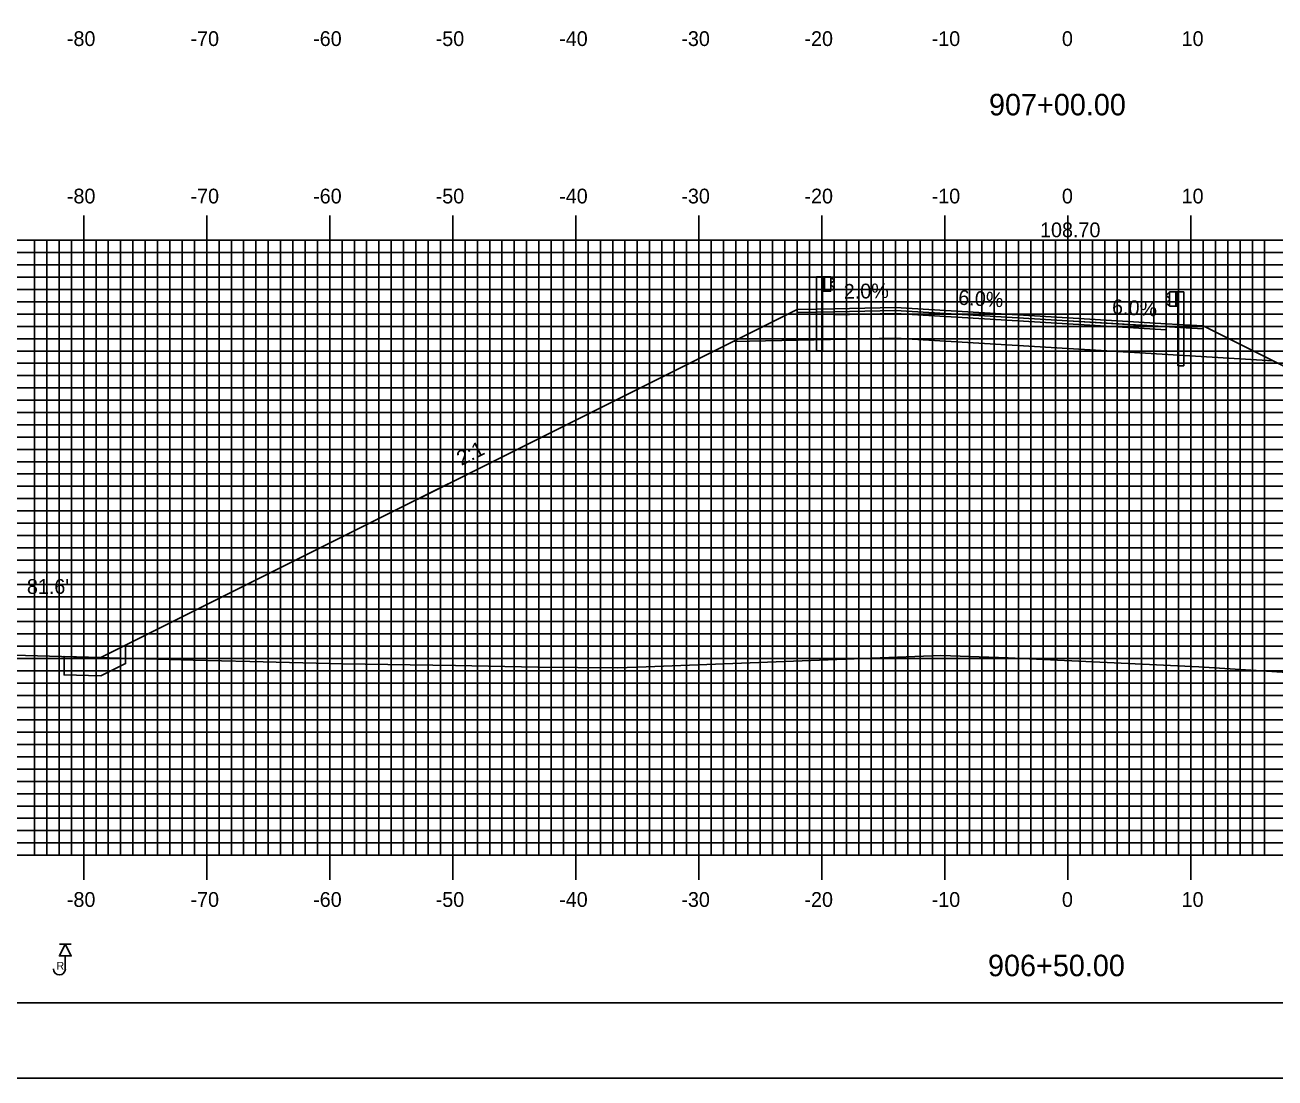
# Model space of a CAD drawing. Extents: x 857897 to 858240, y 364765 to 364985.
# Drawn here: x 857978 to 858079.7, y 364765.2 to 364850.8 of the extents above; entities that cross this region are included whole.
import ezdxf

# ---------------------------------------------------------------- set-up
doc = ezdxf.new("R2010")
doc.units = 0
for name, color, linetype in [('ANNOTATION', 7, 'Continuous'), ('BORDER', 7, 'Continuous'), ('BORING - REFUSAL', 7, 'Continuous'), ('D_Guardrail_Beam_Lt', 7, 'Continuous'), ('D_Guardrail_Beam_Rt', 7, 'Continuous'), ('D_Roadway_Centerline', 7, 'Continuous'), ('D_Roadway_Centerline_Text', 7, 'Continuous'), ('D_Roadway_Edge_Shoulder', 7, 'Continuous'), ('D_Roadway_Edge_TW', 7, 'Continuous'), ('D_Roadway_FinishedGrade', 7, 'Continuous'), ('D_Roadway_Pavement', 7, 'Continuous'), ('D_Roadway_SlopeLines', 7, 'Continuous'), ('D_Roadway_SubGrade', 7, 'Continuous'), ('D_Text_Standard', 7, 'Continuous'), ('H_V ANNOTATION', 7, 'Continuous'), ('MAJOR', 7, 'Continuous'), ('MINOR', 7, 'Continuous'), ('PLOT BOUNDARY', 7, 'Continuous'), ('S_Roadway_Centerline', 7, 'Continuous')]:
    doc.layers.add(name, color=color, linetype=linetype)

msp = doc.modelspace()

# ---------------------------------------------------------------- linework, layer by layer
at = {"layer": 'BORDER'}
msp.add_lwpolyline([(857913.22, 364771.3), (858233.22, 364771.3), (858233.22, 364981.3), (857913.22, 364981.3)], close=True, dxfattribs=at)
at = {"layer": 'BORING - REFUSAL'}
for p, q in [((857981.8, 364776.07), (857980.84, 364776.07)), ((857981.32, 364775.11), (857981.32, 364774.05))]:
    msp.add_line(p, q, dxfattribs=at)
msp.add_lwpolyline([(857981.32, 364776.07), (857981.8, 364775.11), (857980.84, 364775.11)], close=True, dxfattribs=at)
msp.add_arc((857980.84, 364774.05), 0.485, 180, 0, dxfattribs=at)
at = {"layer": 'D_Guardrail_Beam_Lt'}
for p, q in [((858042.39, 364830.32), (858042.39, 364824.32)), ((858042.86, 364830.32), (858042.39, 364830.32)), ((858043.55, 364830.32), (858042.86, 364830.32)), ((858042.86, 364830.32), (858042.86, 364829.16)), ((858042.92, 364830.32), (858042.92, 364829.16)), ((858043.03, 364830.32), (858043.03, 364829.16)), ((858043.55, 364829.16), (858043.55, 364830.32)), ((858043.55, 364830.24), (858043.62, 364830.22)), ((858043.55, 364829.77), (858043.55, 364829.7)), ((858043.78, 364829.97), (858043.59, 364829.84)), ((858043.59, 364829.64), (858043.78, 364829.5)), ((858043.64, 364830.22), (858043.78, 364830.12)), ((858042.86, 364829.16), (858043.55, 364829.16)), ((858042.88, 364824.32), (858042.88, 364829.16)), ((858043.62, 364829.25), (858043.55, 364829.24)), ((858043.78, 364829.36), (858043.64, 364829.26)), ((858042.88, 364824.32), (858042.39, 364824.32))]:
    msp.add_line(p, q, dxfattribs=at)
for centre, major_axis, start_param, end_param in [((858043.63, 364829.77), (-0.0789, 0), 5.323254, 6.283185), ((858043.63, 364829.7), (-0.0789, 0), 6.283185, 7.243116), ((858043.62, 364830.18), (0.0417, 0), 0.959931, 1.376053), ((858043.73, 364830.05), (0.0877, 0), 5.323254, 7.243116), ((858043.62, 364829.29), (0.0417, 0), 4.907132, 5.323254), ((858043.73, 364829.43), (0.0877, 0), 5.323254, 7.243116)]:
    msp.add_ellipse(centre, major_axis=major_axis, ratio=0.995501, start_param=start_param, end_param=end_param, dxfattribs=at)
at = {"layer": 'D_Guardrail_Beam_Rt'}
for p, q in [((858071, 364829), (858070.86, 364828.9)), ((858070.86, 364828.75), (858071.05, 364828.62)), ((858071.09, 364829.02), (858071.02, 364829)), ((858071.09, 364829.1), (858071.78, 364829.1)), ((858071.09, 364827.94), (858071.09, 364829.1)), ((858071.61, 364829.1), (858071.61, 364827.94)), ((858071.72, 364829.1), (858071.72, 364827.94)), ((858071.78, 364829.1), (858072.25, 364829.1)), ((858071.78, 364829.1), (858071.78, 364827.94)), ((858072.25, 364829.1), (858072.25, 364823.1)), ((858071.05, 364828.42), (858070.86, 364828.28)), ((858070.86, 364828.14), (858071, 364828.04)), ((858071.02, 364828.03), (858071.09, 364828.02)), ((858071.09, 364828.55), (858071.09, 364828.48)), ((858071.78, 364827.94), (858071.09, 364827.94)), ((858071.76, 364823.1), (858071.76, 364827.94)), ((858071.76, 364823.1), (858072.25, 364823.1))]:
    msp.add_line(p, q, dxfattribs=at)
for centre, major_axis, start_param, end_param in [((858070.91, 364828.83), (-0.0877, 0), 5.323254, 7.243116), ((858071.03, 364828.96), (-0.0417, 0), 4.907132, 5.323254), ((858071.01, 364828.55), (0.0789, 0), 0, 0.959931), ((858070.91, 364828.21), (-0.0877, 0), 5.323254, 7.243116), ((858071.03, 364828.07), (-0.0417, 0), 0.959931, 1.376053), ((858071.01, 364828.48), (0.0789, 0), 5.323254, 6.283185)]:
    msp.add_ellipse(centre, major_axis=major_axis, ratio=0.995501, start_param=start_param, end_param=end_param, dxfattribs=at)
at = {"layer": 'D_Roadway_Centerline'}
msp.add_lwpolyline([(857984.22, 364799.38), (858035.61, 364825.07), (858040.82, 364827.68), (858043.82, 364827.74), (858048.82, 364827.84), (858062.82, 364827), (858070.82, 364826.52), (858073.82, 364826.34), (858079.5, 364823.5), (858128.75, 364798.87)], dxfattribs=at)
at = {"layer": 'D_Roadway_Edge_Shoulder'}
for points in [[(858048.82, 364827.84), (858043.82, 364827.74), (858043.82, 364827.74), (858040.82, 364827.68), (858040.82, 364827.43), (858043.82, 364827.49), (858048.82, 364827.59)], [(858062.82, 364827), (858070.82, 364826.52), (858070.82, 364826.52), (858073.82, 364826.34), (858073.82, 364826.09), (858062.82, 364826.75)]]:
    msp.add_lwpolyline(points, close=True, dxfattribs=at)
at = {"layer": 'D_Roadway_Edge_TW'}
msp.add_lwpolyline([(858048.82, 364827.84), (858062.82, 364827), (858062.82, 364826.75), (858048.82, 364827.59)], close=True, dxfattribs=at)
at = {"layer": 'D_Roadway_FinishedGrade'}
for points in [[(857986.22, 364800.38), (857986.22, 364798.88), (857984.22, 364797.88), (857981.22, 364797.96), (857981.22, 364799.46), (857984.22, 364799.38)], [(857981.22, 364799.46), (857981.22, 364797.96), (857984.22, 364797.88), (857986.22, 364798.88), (857986.22, 364800.38), (857984.22, 364799.38)]]:
    msp.add_lwpolyline(points, close=True, dxfattribs=at)
at = {"layer": 'D_Roadway_Pavement'}
for points in [[(858048.82, 364827.59), (858043.82, 364827.49), (858043.82, 364827.24), (858048.82, 364827.34)], [(858048.82, 364827.59), (858062.82, 364826.75), (858062.82, 364826.5), (858048.82, 364827.34)]]:
    msp.add_lwpolyline(points, close=True, dxfattribs=at)
for points in [[(858062.82, 364826.75), (858062.82, 364826.5)], [(858062.82, 364826.75), (858062.82, 364826.5)], [(858062.82, 364826.75), (858062.82, 364826.5)], [(858062.82, 364826.75), (858070.82, 364826.27), (858070.82, 364826.02), (858062.82, 364826.5)]]:
    msp.add_lwpolyline(points, dxfattribs=at)
at = {"layer": 'D_Roadway_SlopeLines'}
for points in [[(858040.82, 364827.68), (857984.22, 364799.38)], [(858073.82, 364826.34), (858128.75, 364798.87)]]:
    msp.add_lwpolyline(points, dxfattribs=at)
at = {"layer": 'D_Roadway_SubGrade'}
for points in [[(858048.82, 364827.34), (858043.82, 364827.24), (858043.82, 364827.49), (858040.82, 364827.43), (858040.82, 364827.68), (858035.61, 364825.07), (858048.82, 364825.34)], [(858048.82, 364827.34), (858062.82, 364826.5), (858062.82, 364824.5), (858048.82, 364825.34)], [(858062.82, 364826.5), (858062.82, 364826.75), (858073.82, 364826.09), (858073.82, 364826.34), (858079.5, 364823.5), (858062.82, 364824.5)]]:
    msp.add_lwpolyline(points, close=True, dxfattribs=at)
at = {"layer": 'MAJOR'}
for p, q in [((857982.82, 364835.31), (857982.82, 364833.3)), ((857992.82, 364835.31), (857992.82, 364833.3)), ((858002.82, 364835.31), (858002.82, 364833.3)), ((858012.82, 364835.31), (858012.82, 364833.3)), ((858022.82, 364835.31), (858022.82, 364833.3)), ((858032.82, 364835.31), (858032.82, 364833.3)), ((858042.82, 364835.31), (858042.82, 364833.3)), ((858052.82, 364835.31), (858052.82, 364833.3)), ((858062.82, 364835.31), (858062.82, 364833.3)), ((858072.82, 364835.31), (858072.82, 364833.3)), ((857922.82, 364833.3), (858202.82, 364833.3)), ((857922.82, 364833.3), (858202.82, 364833.3)), ((857982.82, 364783.3), (857982.82, 364833.3)), ((857992.82, 364783.3), (857992.82, 364833.3)), ((858002.82, 364783.3), (858002.82, 364833.3)), ((858012.82, 364783.3), (858012.82, 364833.3)), ((858022.82, 364783.3), (858022.82, 364833.3)), ((858032.82, 364783.3), (858032.82, 364833.3)), ((858042.82, 364783.3), (858042.82, 364833.3)), ((858052.82, 364783.3), (858052.82, 364833.3)), ((858062.82, 364783.3), (858062.82, 364833.3)), ((858072.82, 364783.3), (858072.82, 364833.3)), ((857922.82, 364828.3), (858202.82, 364828.3)), ((857922.82, 364823.3), (858202.82, 364823.3)), ((857922.82, 364818.3), (858202.82, 364818.3)), ((857922.82, 364813.3), (858202.82, 364813.3)), ((857922.82, 364808.3), (858202.82, 364808.3)), ((857922.82, 364803.3), (858202.82, 364803.3)), ((857922.82, 364798.3), (858202.82, 364798.3)), ((857922.82, 364793.3), (858202.82, 364793.3)), ((857922.82, 364788.3), (858202.82, 364788.3)), ((857922.82, 364783.3), (858202.82, 364783.3)), ((857922.82, 364783.3), (858202.82, 364783.3)), ((857982.82, 364781.3), (857982.82, 364783.3)), ((857992.82, 364781.3), (857992.82, 364783.3)), ((858002.82, 364781.3), (858002.82, 364783.3)), ((858012.82, 364781.3), (858012.82, 364783.3)), ((858022.82, 364781.3), (858022.82, 364783.3)), ((858032.82, 364781.3), (858032.82, 364783.3)), ((858042.82, 364781.3), (858042.82, 364783.3)), ((858052.82, 364781.3), (858052.82, 364783.3)), ((858062.82, 364781.3), (858062.82, 364783.3)), ((858072.82, 364781.3), (858072.82, 364783.3))]:
    msp.add_line(p, q, dxfattribs=at)
at = {"layer": 'MINOR'}
for p, q in [((857978.82, 364783.3), (857978.82, 364833.3)), ((857979.82, 364783.3), (857979.82, 364833.3)), ((857980.82, 364783.3), (857980.82, 364833.3)), ((857981.82, 364783.3), (857981.82, 364833.3)), ((857983.82, 364783.3), (857983.82, 364833.3)), ((857984.82, 364783.3), (857984.82, 364833.3)), ((857985.82, 364783.3), (857985.82, 364833.3)), ((857986.82, 364783.3), (857986.82, 364833.3)), ((857987.82, 364783.3), (857987.82, 364833.3)), ((857988.82, 364783.3), (857988.82, 364833.3)), ((857989.82, 364783.3), (857989.82, 364833.3)), ((857990.82, 364783.3), (857990.82, 364833.3)), ((857991.82, 364783.3), (857991.82, 364833.3)), ((857993.82, 364783.3), (857993.82, 364833.3)), ((857994.82, 364783.3), (857994.82, 364833.3)), ((857995.82, 364783.3), (857995.82, 364833.3)), ((857996.82, 364783.3), (857996.82, 364833.3)), ((857997.82, 364783.3), (857997.82, 364833.3)), ((857998.82, 364783.3), (857998.82, 364833.3)), ((857999.82, 364783.3), (857999.82, 364833.3)), ((858000.82, 364783.3), (858000.82, 364833.3)), ((858001.82, 364783.3), (858001.82, 364833.3)), ((858003.82, 364783.3), (858003.82, 364833.3)), ((858004.82, 364783.3), (858004.82, 364833.3)), ((858005.82, 364783.3), (858005.82, 364833.3)), ((858006.82, 364783.3), (858006.82, 364833.3)), ((858007.82, 364783.3), (858007.82, 364833.3)), ((858008.82, 364783.3), (858008.82, 364833.3)), ((858009.82, 364783.3), (858009.82, 364833.3)), ((858010.82, 364783.3), (858010.82, 364833.3)), ((858011.82, 364783.3), (858011.82, 364833.3)), ((858013.82, 364783.3), (858013.82, 364833.3)), ((858014.82, 364783.3), (858014.82, 364833.3)), ((858015.82, 364783.3), (858015.82, 364833.3)), ((858016.82, 364783.3), (858016.82, 364833.3)), ((858017.82, 364783.3), (858017.82, 364833.3)), ((858018.82, 364783.3), (858018.82, 364833.3)), ((858019.82, 364783.3), (858019.82, 364833.3)), ((858020.82, 364783.3), (858020.82, 364833.3)), ((858021.82, 364783.3), (858021.82, 364833.3)), ((858023.82, 364783.3), (858023.82, 364833.3)), ((858024.82, 364783.3), (858024.82, 364833.3)), ((858025.82, 364783.3), (858025.82, 364833.3)), ((858026.82, 364783.3), (858026.82, 364833.3)), ((858027.82, 364783.3), (858027.82, 364833.3)), ((858028.82, 364783.3), (858028.82, 364833.3)), ((858029.82, 364783.3), (858029.82, 364833.3)), ((858030.82, 364783.3), (858030.82, 364833.3)), ((858031.82, 364783.3), (858031.82, 364833.3)), ((858033.82, 364783.3), (858033.82, 364833.3)), ((858034.82, 364783.3), (858034.82, 364833.3)), ((858035.82, 364783.3), (858035.82, 364833.3)), ((858036.82, 364783.3), (858036.82, 364833.3)), ((858037.82, 364783.3), (858037.82, 364833.3)), ((858038.82, 364783.3), (858038.82, 364833.3)), ((858039.82, 364783.3), (858039.82, 364833.3)), ((858040.82, 364783.3), (858040.82, 364833.3)), ((858041.82, 364783.3), (858041.82, 364833.3)), ((858043.82, 364783.3), (858043.82, 364833.3)), ((858044.82, 364783.3), (858044.82, 364833.3)), ((858045.82, 364783.3), (858045.82, 364833.3)), ((858046.82, 364783.3), (858046.82, 364833.3)), ((858047.82, 364783.3), (858047.82, 364833.3)), ((858048.82, 364783.3), (858048.82, 364833.3)), ((858049.82, 364783.3), (858049.82, 364833.3)), ((858050.82, 364783.3), (858050.82, 364833.3)), ((858051.82, 364783.3), (858051.82, 364833.3)), ((858053.82, 364783.3), (858053.82, 364833.3)), ((858054.82, 364783.3), (858054.82, 364833.3)), ((858055.82, 364783.3), (858055.82, 364833.3)), ((858056.82, 364783.3), (858056.82, 364833.3)), ((858057.82, 364783.3), (858057.82, 364833.3)), ((858058.82, 364783.3), (858058.82, 364833.3)), ((858059.82, 364783.3), (858059.82, 364833.3)), ((858060.82, 364783.3), (858060.82, 364833.3)), ((858061.82, 364783.3), (858061.82, 364833.3)), ((858063.82, 364783.3), (858063.82, 364833.3)), ((858064.82, 364783.3), (858064.82, 364833.3)), ((858065.82, 364783.3), (858065.82, 364833.3)), ((858066.82, 364783.3), (858066.82, 364833.3)), ((858067.82, 364783.3), (858067.82, 364833.3)), ((858068.82, 364783.3), (858068.82, 364833.3)), ((858069.82, 364783.3), (858069.82, 364833.3)), ((858070.82, 364783.3), (858070.82, 364833.3)), ((858071.82, 364783.3), (858071.82, 364833.3)), ((858073.82, 364783.3), (858073.82, 364833.3)), ((858074.82, 364783.3), (858074.82, 364833.3)), ((858075.82, 364783.3), (858075.82, 364833.3)), ((858076.82, 364783.3), (858076.82, 364833.3)), ((858077.82, 364783.3), (858077.82, 364833.3)), ((858078.82, 364783.3), (858078.82, 364833.3)), ((857922.82, 364832.3), (858202.82, 364832.3)), ((857922.82, 364831.3), (858202.82, 364831.3)), ((857922.82, 364830.3), (858202.82, 364830.3)), ((857922.82, 364829.3), (858202.82, 364829.3)), ((857922.82, 364827.3), (858202.82, 364827.3)), ((857922.82, 364826.3), (858202.82, 364826.3)), ((857922.82, 364825.3), (858202.82, 364825.3)), ((857922.82, 364824.3), (858202.82, 364824.3)), ((857922.82, 364822.3), (858202.82, 364822.3)), ((857922.82, 364821.3), (858202.82, 364821.3)), ((857922.82, 364820.3), (858202.82, 364820.3)), ((857922.82, 364819.3), (858202.82, 364819.3)), ((857922.82, 364817.3), (858202.82, 364817.3)), ((857922.82, 364816.3), (858202.82, 364816.3)), ((857922.82, 364815.3), (858202.82, 364815.3)), ((857922.82, 364814.3), (858202.82, 364814.3)), ((857922.82, 364812.3), (858202.82, 364812.3)), ((857922.82, 364811.3), (858202.82, 364811.3)), ((857922.82, 364810.3), (858202.82, 364810.3)), ((857922.82, 364809.3), (858202.82, 364809.3)), ((857922.82, 364807.3), (858202.82, 364807.3)), ((857922.82, 364806.3), (858202.82, 364806.3)), ((857922.82, 364805.3), (858202.82, 364805.3)), ((857922.82, 364804.3), (858202.82, 364804.3)), ((857922.82, 364802.3), (858202.82, 364802.3)), ((857922.82, 364801.3), (858202.82, 364801.3)), ((857922.82, 364800.3), (858202.82, 364800.3)), ((857922.82, 364799.3), (858202.82, 364799.3)), ((857922.82, 364797.3), (858202.82, 364797.3)), ((857922.82, 364796.3), (858202.82, 364796.3)), ((857922.82, 364795.3), (858202.82, 364795.3)), ((857922.82, 364794.3), (858202.82, 364794.3)), ((857922.82, 364792.3), (858202.82, 364792.3)), ((857922.82, 364791.3), (858202.82, 364791.3)), ((857922.82, 364790.3), (858202.82, 364790.3)), ((857922.82, 364789.3), (858202.82, 364789.3)), ((857922.82, 364787.3), (858202.82, 364787.3)), ((857922.82, 364786.3), (858202.82, 364786.3)), ((857922.82, 364785.3), (858202.82, 364785.3)), ((857922.82, 364784.3), (858202.82, 364784.3))]:
    msp.add_line(p, q, dxfattribs=at)
at = {"layer": 'PLOT BOUNDARY'}
msp.add_lwpolyline([(857897.03, 364765.18), (858237.03, 364765.18), (858237.03, 364985.18), (857897.03, 364985.18)], close=True, dxfattribs=at)
at = {"layer": 'S_Roadway_Centerline'}
msp.add_lwpolyline([(857922.82, 364814.97), (857941.83, 364809.36), (857945.12, 364808.11), (857951.95, 364805.25), (857962.43, 364800.71), (857972.2, 364799.71), (857991.73, 364799.17), (857996.31, 364799.06), (858003.85, 364798.87), (858013.03, 364798.72), (858019.74, 364798.6), (858026.22, 364798.53), (858028.55, 364798.62), (858052.49, 364799.53), (858057.96, 364799.36), (858073.46, 364798.61), (858081.08, 364798.12)], dxfattribs=at)

# ---------------------------------------------------------------- texts
at = {"layer": 'ANNOTATION'}
for s, rotation, p in [('2.0%', 1.1458, (858044.62, 364828.54)), ('6.0%', 356.5664, (858053.89, 364828.07)), ('6.0%', 356.5664, (858066.39, 364827.32)), ('2:1', 26.5651, (858013.52, 364814.95))]:
    msp.add_text(s, height=1.2, rotation=rotation, dxfattribs=at).set_placement(p)
at = {"layer": 'BORING - REFUSAL'}
msp.add_text('R', height=0.64, dxfattribs=at).set_placement((857980.61, 364773.99))
at = {"layer": 'D_Roadway_Centerline_Text'}
msp.add_text('108.70', height=1.2, dxfattribs=at).set_placement((858060.56, 364833.55))
at = {"layer": 'D_Text_Standard'}
msp.add_text("81.6'", height=1.2, dxfattribs=at).set_placement((857978.2, 364804.55))
at = {"layer": 'H_V ANNOTATION'}
for s, height, p in [('-80', 1.2, (857981.45, 364849.1)), ('-70', 1.2, (857991.5, 364849.1)), ('-60', 1.2, (858001.47, 364849.1)), ('-50', 1.2, (858011.43, 364849.1)), ('-40', 1.2, (858021.47, 364849.1)), ('-30', 1.2, (858031.4, 364849.1)), ('-20', 1.2, (858041.41, 364849.1)), ('-10', 1.2, (858051.75, 364849.1)), ('0', 1.2, (858062.34, 364849.1)), ('10', 1.2, (858072.07, 364849.1)), ('907+00.00', 1.75, (858056.41, 364843.46)), ('-80', 1.2, (857981.45, 364836.3)), ('-70', 1.2, (857991.5, 364836.3)), ('-60', 1.2, (858001.47, 364836.3)), ('-50', 1.2, (858011.43, 364836.3)), ('-40', 1.2, (858021.47, 364836.3)), ('-30', 1.2, (858031.4, 364836.3)), ('-20', 1.2, (858041.41, 364836.3)), ('-10', 1.2, (858051.75, 364836.3)), ('0', 1.2, (858062.34, 364836.3)), ('10', 1.2, (858072.07, 364836.3)), ('-80', 1.2, (857981.45, 364779.1)), ('-70', 1.2, (857991.5, 364779.1)), ('-60', 1.2, (858001.47, 364779.1)), ('-50', 1.2, (858011.43, 364779.1)), ('-40', 1.2, (858021.47, 364779.1)), ('-30', 1.2, (858031.4, 364779.1)), ('-20', 1.2, (858041.41, 364779.1)), ('-10', 1.2, (858051.75, 364779.1)), ('0', 1.2, (858062.34, 364779.1)), ('10', 1.2, (858072.07, 364779.1)), ('906+50.00', 1.75, (858056.33, 364773.46))]:
    msp.add_text(s, height=height, dxfattribs=at).set_placement(p)

doc.saveas('drawing.dxf')
